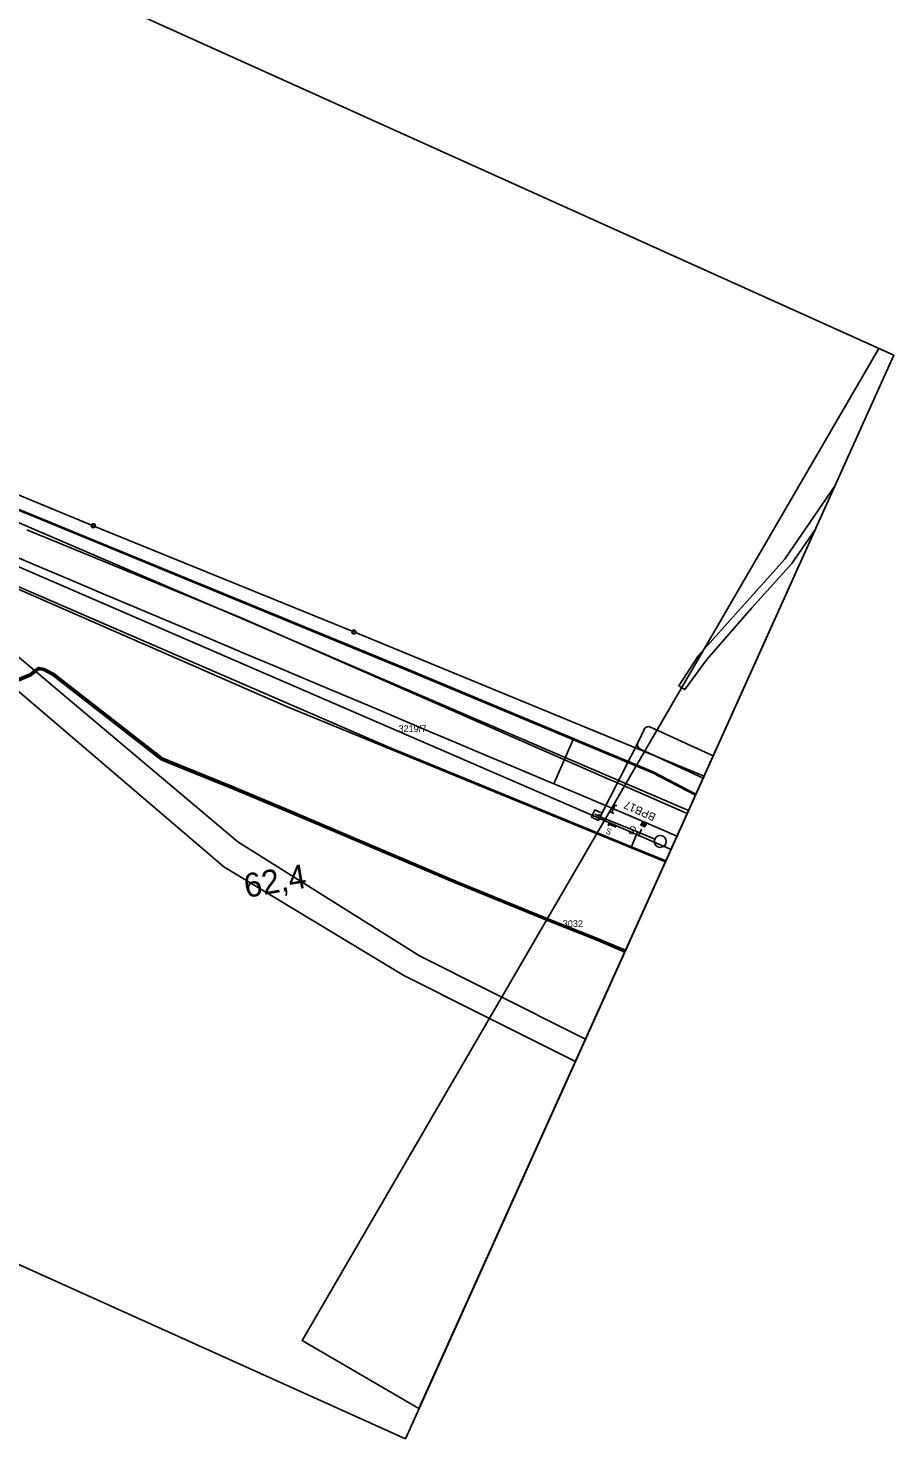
# Model space of a CAD drawing. Extents: x -621716 to -621020, y -1122350 to -1121821.
# Drawn here: x -621236.3 to -621020, y -1122350.4 to -1121998 of the extents above; entities that cross this region are included whole.
import ezdxf

# ---------------------------------------------------------------- set-up
doc = ezdxf.new("R2010")
doc.units = 0
for name, color, linetype in [('CETIN', 7, 'Continuous'), ('hm', 7, 'Continuous'), ('HranDP', 7, 'Continuous'), ('Hranice parcel', 7, 'Continuous'), ('itself', 7, 'Continuous'), ('Level 10', 7, 'Continuous'), ('lomové body trasa', 7, 'Continuous'), ('Parcelní čísla', 7, 'Continuous'), ('PS 06-14-01_trasa_sdělovací_nové', 7, 'Continuous'), ('PS6-14-01_bubliny', 7, 'Continuous'), ('Rámečky-tisk', 7, 'Continuous'), ('SSZT', 7, 'Continuous'), ('SSZT-DK', 7, 'Continuous'), ('STANICENI NOVE HM', 7, 'Continuous'), ('Vrstva 1', 7, 'Continuous'), ('Vrstva 2', 7, 'Continuous'), ('Vrstva 3', 7, 'Continuous'), ('Vrstva 6', 7, 'Continuous'), ('Věcná břemena k části', 7, 'Continuous'), ('Značky bodu BP', 7, 'Continuous'), ('ČD-T', 7, 'Continuous')]:
    doc.layers.add(name, color=color, linetype=linetype)

# ---------------------------------------------------------------- blocks, each defined once
blk = doc.blocks.new('C535')
at = {"layer": 'Level 10'}
for p, q in [((-0.5, 0.5), (0.5, 0.5)), ((0, 0.5), (0, -0.5))]:
    blk.add_line(p, q, dxfattribs=at)
blk.add_lwpolyline([(-1, 1), (1, 1), (1, -1), (-1, -1), (-1, 1)], dxfattribs=at)

msp = doc.modelspace()

# ---------------------------------------------------------------- linework, layer by layer
at = {"layer": 'CETIN'}
msp.add_lwpolyline([(-621391.64, -1122051.98), (-621348.65, -1122072.13), (-621239.56, -1122121.11), (-621071.24, -1122193.44)], dxfattribs=at)
at = {"layer": 'hm'}
for p, q in [((-621236.12, -1122131.3), (-621236.12, -1122131.3)), ((-621143.95, -1122170.24), (-621143.95, -1122170.24))]:
    msp.add_line(p, q, dxfattribs=at)
at = {"layer": 'HranDP'}
for points in [[(-621071.57, -1122194.18), (-621089.46, -1122186.34), (-621091.58, -1122185.41), (-621183.06, -1122145.34), (-621236.6, -1122123.3)], [(-621077.02, -1122206.26), (-621096.79, -1122198.16), (-621171.69, -1122167.46), (-621240.3, -1122137.45)]]:
    msp.add_lwpolyline(points, dxfattribs=at)
at = {"layer": 'Hranice parcel'}
for points in [[(-621316.28, -1121963.73), (-621318.05, -1121968.15), (-621373.38, -1122024.18), (-621378.72, -1122030.05), (-621381.72, -1122035.12), (-621383.2, -1122041.04), (-621383.06, -1122046.37), (-621381.45, -1122051.28), (-621377.34, -1122056.11), (-621371.25, -1122059.79), (-621220, -1122122.28), (-621154.89, -1122148.82), (-621067.38, -1122184.88)], [(-621187.4, -1122207.5), (-621250, -1122154.05), (-621256.5, -1122148.5), (-621279.33, -1122126.02), (-621347.74, -1122094.36), (-621373.17, -1122084.12), (-621407.84, -1122078), (-621413.72, -1122077.04), (-621414.64, -1122076.64)], [(-621039.54, -1122123.11), (-621045.46, -1122131.72), (-621055.41, -1122142.78), (-621066.65, -1122155.68), (-621072.18, -1122163.23), (-621073.7, -1122162.28), (-621068.77, -1122154.75), (-621047.24, -1122130.75), (-621034.62, -1122112.2)], [(-621071.57, -1122194.18), (-621089.46, -1122186.34), (-621091.58, -1122185.41), (-621183.06, -1122145.34), (-621236.6, -1122123.3)], [(-621077.02, -1122206.26), (-621096.79, -1122198.16), (-621171.69, -1122167.46), (-621240.3, -1122137.45)], [(-621247, -1122148.15), (-621183.91, -1122201.29), (-621138.49, -1122229.74), (-621120.6, -1122238.74), (-621097.01, -1122250.61)], [(-621099.51, -1122256.14), (-621123.45, -1122244.15), (-621142.42, -1122234.65), (-621187.4, -1122207.5)]]:
    msp.add_lwpolyline(points, dxfattribs=at)
at = {"layer": 'itself'}
msp.add_lwpolyline([(-621087.09, -1122228.59), (-621094.27, -1122225.57), (-621106.27, -1122220.82), (-621129.5, -1122211.33), (-621170.86, -1122193.72), (-621185.48, -1122187.6), (-621197, -1122182.95), (-621202.94, -1122180.53), (-621213.65, -1122172.18), (-621230.03, -1122159.41), (-621232.32, -1122158.2), (-621233.62, -1122157.94), (-621235.74, -1122159.55), (-621240.06, -1122161.38)], dxfattribs=at)
at = {"layer": 'lomové body trasa'}
msp.add_line((-621093.31, -1122195.04), (-621084.03, -1122198.76), dxfattribs=at)
at = {"layer": 'PS 06-14-01_trasa_sdělovací_nové'}
msp.add_lwpolyline([(-621076.91, -1122206.02), (-621085.52, -1122202.49), (-621084.03, -1122198.76), (-621093.31, -1122195.04)], dxfattribs=at)
at = {"layer": 'PS6-14-01_bubliny'}
for p, q in [((-621082.37, -1122173.2), (-621083.89, -1122176.52)), ((-621065.09, -1122179.79), (-621080.75, -1122172.6)), ((-621093.31, -1122195.04), (-621083.13, -1122174.86)), ((-621083.29, -1122178.14), (-621067.59, -1122185.35)), ((-621067.59, -1122185.35), (-621065.09, -1122179.79))]:
    msp.add_line(p, q, dxfattribs=at)
for centre, start, end in [((-621081.26, -1122173.71), 65.3299, 155.3299), ((-621082.78, -1122177.03), 155.3299, 245.3299)]:
    msp.add_arc(centre, 1.22, start, end, dxfattribs=at)
at = {"layer": 'Rámečky-tisk'}
for points in [[(-621594.3, -1121820.78), (-621716.36, -1122091.54), (-621142.02, -1122350.45)], [(-621142.02, -1122350.45), (-621019.96, -1122079.69), (-621594.3, -1121820.78)], [(-621023.68, -1122078.01), (-621167.83, -1122325.92), (-621138.62, -1122342.9)], [(-621138.62, -1122342.9), (-621019.96, -1122079.69), (-621023.68, -1122078.01)]]:
    msp.add_lwpolyline(points, dxfattribs=at)
at = {"layer": 'SSZT'}
msp.add_lwpolyline([(-621464.69, -1122038.44), (-621426.39, -1122054.01), (-621396.86, -1122066.88), (-621366.19, -1122078.92), (-621242.28, -1122131.01), (-621075.62, -1122203.15)], dxfattribs=at)
at = {"layer": 'SSZT-DK'}
msp.add_line((-621104.92, -1122186.78), (-621100.09, -1122175.73), dxfattribs=at)
msp.add_lwpolyline([(-621652.1, -1121948.99), (-621602.77, -1121970.18), (-621587.01, -1121980.11), (-621563.13, -1121987.74), (-621510.81, -1122009.58), (-621450.27, -1122033.62), (-621416.07, -1122045.03), (-621374.72, -1122063.23), (-621336.47, -1122079.96), (-621283.95, -1122100.3), (-621235.89, -1122119.6), (-621141.63, -1122158.36), (-621080.25, -1122184.04), (-621069.51, -1122189.6)], dxfattribs=at)
at = {"layer": 'Vrstva 1'}
for points in [[(-621085.52, -1122202.49), (-621145.97, -1122177.73), (-621266.9, -1122125.34), (-621335.07, -1122094.53), (-621348.64, -1122088.4), (-621357.58, -1122084.62), (-621357.08, -1122083.45), (-621364.5, -1122080.32), (-621400.77, -1122065), (-621401.81, -1122066.92), (-621406.73, -1122065.04)], [(-621242.46, -1122128.76), (-621234.48, -1122132.13), (-621226.13, -1122135.65), (-621217.53, -1122139.28), (-621208.79, -1122142.96), (-621200.3, -1122146.55), (-621191.38, -1122150.31), (-621182.22, -1122154.18), (-621173.81, -1122157.72), (-621165.57, -1122161.19), (-621156.77, -1122164.91), (-621149.67, -1122167.91), (-621143.22, -1122170.63), (-621137.43, -1122173.08), (-621129.68, -1122176.35), (-621122.01, -1122179.58), (-621114.57, -1122182.71), (-621106.5, -1122186.11), (-621098.7, -1122189.4), (-621092.01, -1122192.21), (-621090.02, -1122193.05), (-621083.15, -1122195.96), (-621075.1, -1122199.44), (-621074.14, -1122199.87)], [(-621083.39, -1122199.04), (-621084.03, -1122198.76), (-621085.52, -1122202.49)], [(-621076.91, -1122206.02), (-621080.17, -1122204.68), (-621085.52, -1122202.49)]]:
    msp.add_lwpolyline(points, dxfattribs=at)
at = {"layer": 'Vrstva 2'}
for p, q in [((-621083, -1122198.12), (-621083.78, -1122199.96)), ((-621083.12, -1122197.06), (-621081.8, -1122196.57)), ((-621083.04, -1122196.89), (-621081.97, -1122196.5)), ((-621083.03, -1122197.16), (-621081.8, -1122196.71)), ((-621082.96, -1122196.72), (-621082.14, -1122196.42)), ((-621082.88, -1122196.55), (-621082.31, -1122196.34)), ((-621082.86, -1122197.24), (-621081.88, -1122196.88)), ((-621082.8, -1122196.38), (-621082.48, -1122196.26)), ((-621082.73, -1122196.21), (-621082.65, -1122196.19)), ((-621082.69, -1122197.32), (-621081.96, -1122197.05)), ((-621082.52, -1122197.4), (-621082.03, -1122197.22)), ((-621082.36, -1122197.48), (-621082.11, -1122197.39)), ((-621079.7, -1122200.6), (-621083.39, -1122199.04))]:
    msp.add_line(p, q, dxfattribs=at)
msp.add_lwpolyline([(-621082.7, -1122196.16), (-621081.75, -1122196.6), (-621082.19, -1122197.55), (-621083.14, -1122197.11)], close=True, dxfattribs=at)
msp.add_lwpolyline([(-621082.7, -1122196.16), (-621081.75, -1122196.6), (-621082.19, -1122197.55), (-621083.14, -1122197.11)], close=True, dxfattribs=at)
msp.add_circle((-621078.32, -1122201.18), 1.5, dxfattribs=at)
at = {"layer": 'Vrstva 3'}
for p, q in [((-621090.87, -1122193.78), (-621089.95, -1122194.16)), ((-621089.64, -1122192.13), (-621090.41, -1122193.97)), ((-621090.1, -1122191.93), (-621089.18, -1122192.32))]:
    msp.add_line(p, q, dxfattribs=at)
at = {"layer": 'Vrstva 6'}
for p, q in [((-621090.97, -1122196.38), (-621091.37, -1122197.3)), ((-621089.36, -1122197.63), (-621091.17, -1122196.84))]:
    msp.add_line(p, q, dxfattribs=at)
at = {"layer": 'Věcná břemena k části'}
msp.add_line((-621087.19, -1122228.82), (-621086.99, -1122228.37), dxfattribs=at)
msp.add_lwpolyline([(-621234.35, -1122158.81), (-621234.74, -1122158.48), (-621235.87, -1122159.33), (-621240.17, -1122161.16), (-621241.08, -1122161.66), (-621240.68, -1122162.01), (-621239.95, -1122161.6), (-621235.61, -1122159.77)], close=True, dxfattribs=at)
msp.add_lwpolyline([(-621086.99, -1122228.37), (-621094.18, -1122225.34), (-621106.18, -1122220.59), (-621129.4, -1122211.1), (-621170.76, -1122193.49), (-621185.38, -1122187.37), (-621196.91, -1122182.72), (-621202.81, -1122180.31), (-621229.89, -1122159.2), (-621232.24, -1122157.96), (-621233.68, -1122157.67), (-621234.74, -1122158.48), (-621234.35, -1122158.81), (-621233.56, -1122158.21), (-621232.4, -1122158.44), (-621230.17, -1122159.62), (-621203.07, -1122180.75), (-621197.09, -1122183.18), (-621185.58, -1122187.83), (-621170.96, -1122193.95), (-621129.6, -1122211.56), (-621106.36, -1122221.05), (-621094.36, -1122225.8), (-621087.19, -1122228.82)], dxfattribs=at)
at = {"layer": 'Značky bodu BP'}
for centre, radius in [((-621220, -1122122.28), 0.5), ((-621220, -1122122.28), 0.0303), ((-621154.89, -1122148.82), 0.5), ((-621154.89, -1122148.82), 0.0303)]:
    msp.add_circle(centre, radius, dxfattribs=at)
at = {"layer": 'ČD-T'}
msp.add_lwpolyline([(-621651.98, -1121948.73), (-621602.59, -1121969.95), (-621586.83, -1121979.88), (-621562.94, -1121987.51), (-621510.62, -1122009.35), (-621450.08, -1122033.39), (-621415.88, -1122044.8), (-621374.53, -1122062.99), (-621336.28, -1122079.72), (-621283.76, -1122100.06), (-621235.71, -1122119.36), (-621141.45, -1122158.12), (-621080.06, -1122183.8), (-621069.39, -1122189.33)], dxfattribs=at)

# ---------------------------------------------------------------- block references
at = {"layer": 'PS 06-14-01_trasa_sdělovací_nové', "rotation": -115.43387860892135}
msp.add_blockref('C535', (-621094.21, -1122194.6), dxfattribs=at)

# ---------------------------------------------------------------- texts
at = {"layer": 'Parcelní čísla'}
for s, p in [('3219/7', (-621143.74, -1122173.86)), ('3032', (-621102.69, -1122222.58))]:
    msp.add_text(s, height=1.7, dxfattribs=at).set_placement(p)
at = {"layer": 'STANICENI NOVE HM'}
msp.add_text('62,4', height=6, rotation=9.6991, dxfattribs=at).set_placement((-621181.81, -1122215.31))
at = {"layer": 'Vrstva 3'}
for s, p in [('BPB17', (-621079.23, -1122194.37)), ('S', (-621084.1, -1122197.86))]:
    msp.add_text(s, height=2, rotation=155.7341, dxfattribs=at).set_placement(p)
at = {"layer": 'Vrstva 6'}
msp.add_text('S', height=1.5, rotation=336.4373, dxfattribs=at).set_placement((-621092.12, -1122199.11))

doc.saveas('drawing.dxf')
